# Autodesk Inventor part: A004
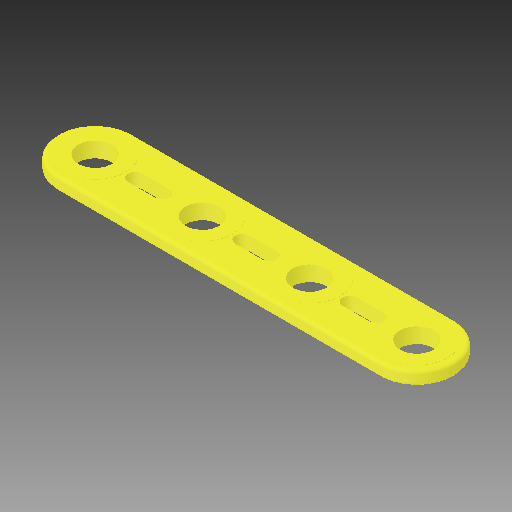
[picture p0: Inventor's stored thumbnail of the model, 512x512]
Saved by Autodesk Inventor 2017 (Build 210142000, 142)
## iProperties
Part Number: A004
Material: Générique
Document SubType Name: Modeling
Designer: ficho
Density: 1 g/cm^3
Appearance: Par défaut
Author: ficho
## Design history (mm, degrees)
feature "Solid1"
node "Solide1"
